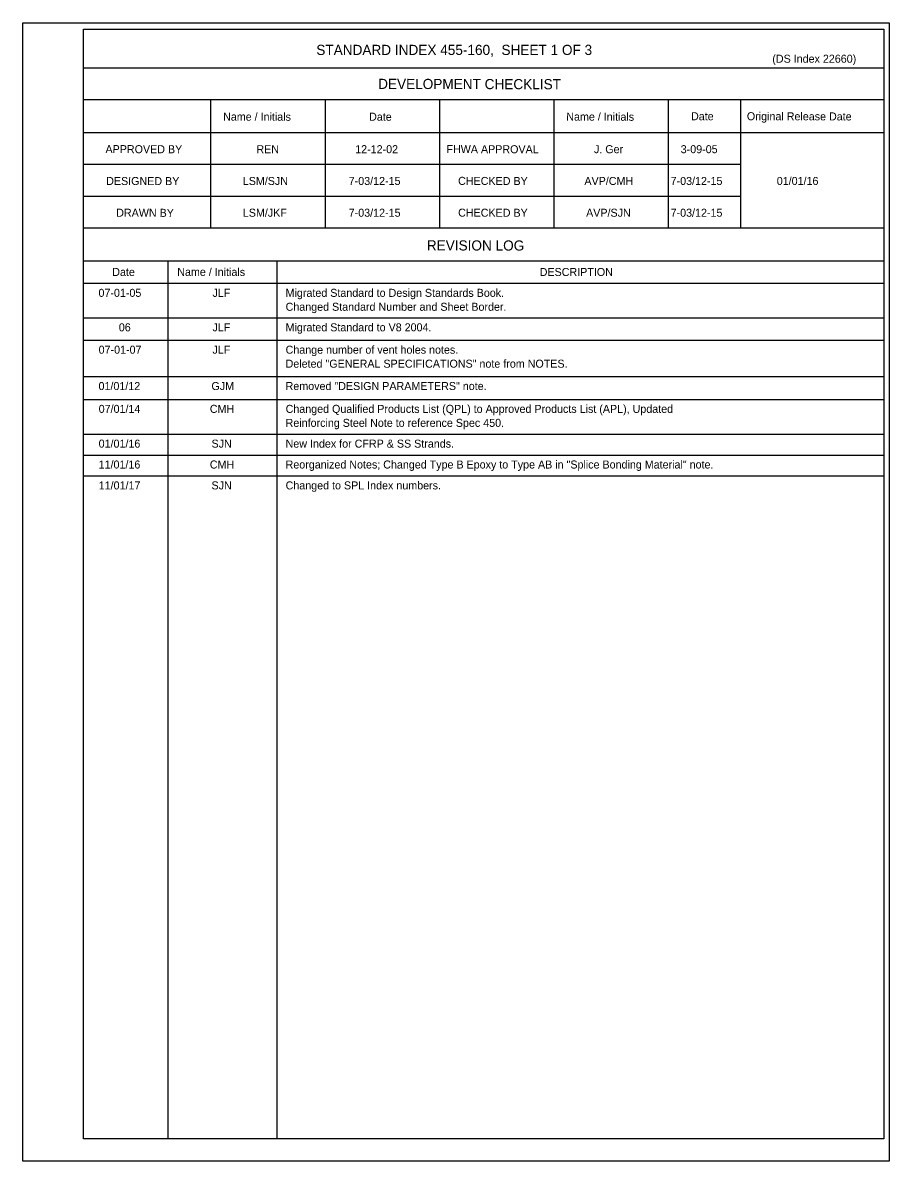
# Model space of a CAD drawing. Extents: x 120462 to 120592, y 120515 to 120635.
# Drawn here: x 120570.2 to 120592.01, y 120600.69 to 120629.36 of the extents above; entities that cross this region are included whole.
import ezdxf

# ---------------------------------------------------------------- set-up
doc = ezdxf.new("R2010")
doc.units = 0
for name, color, linetype in [('AdhocPoint_dp', 7, 'Continuous'), ('Border', 7, 'Continuous'), ('SheetBorder_dp', 7, 'Continuous')]:
    doc.layers.add(name, color=color, linetype=linetype)

msp = doc.modelspace()

# ---------------------------------------------------------------- linework, layer by layer
at = {"layer": 'AdhocPoint_dp'}
for p, q in [((120571.728, 120621.929), (120591.874, 120621.929)), ((120571.728, 120621.365), (120591.874, 120621.365)), ((120571.728, 120620.45), (120591.874, 120620.45)), ((120571.728, 120619.875), (120591.874, 120619.875)), ((120571.728, 120619), (120591.874, 120619)), ((120571.728, 120618.474), (120591.874, 120618.474)), ((120571.728, 120617.948), (120591.874, 120617.948))]:
    msp.add_line(p, q, dxfattribs=at)
at = {"layer": 'Border'}
for p, q in [((120591.874, 120628.217), (120571.727, 120628.217)), ((120591.874, 120627.417), (120571.727, 120627.417)), ((120574.927, 120627.417), (120574.927, 120624.189)), ((120577.807, 120627.417), (120577.807, 120624.189)), ((120580.687, 120627.417), (120580.687, 120624.189)), ((120583.567, 120627.417), (120583.567, 120624.189)), ((120586.447, 120627.417), (120586.447, 120624.189)), ((120588.262, 120627.417), (120588.262, 120624.189)), ((120591.874, 120626.589), (120571.727, 120626.589)), ((120588.262, 120625.789), (120571.727, 120625.789)), ((120588.262, 120624.989), (120571.727, 120624.989)), ((120591.874, 120624.189), (120571.727, 120624.189)), ((120591.874, 120623.361), (120571.727, 120623.361)), ((120573.848, 120623.361), (120573.848, 120601.255)), ((120576.59, 120623.361), (120576.59, 120601.255)), ((120591.874, 120622.797), (120571.727, 120622.797))]:
    msp.add_line(p, q, dxfattribs=at)
msp.add_lwpolyline([(120571.728, 120629.197), (120591.874, 120629.197), (120591.874, 120601.255), (120571.728, 120601.255)], close=True, dxfattribs=at)
at = {"layer": 'SheetBorder_dp'}
msp.add_line((120570.197, 120600.693), (120570.197, 120600.693), dxfattribs=at)
msp.add_lwpolyline([(120570.197, 120629.36), (120592.01, 120629.36), (120592.01, 120600.693), (120570.197, 120600.693)], close=True, dxfattribs=at)

# ---------------------------------------------------------------- texts
at = {"layer": 'Border'}
for s, height, p in [('STANDARD INDEX 455-160,  SHEET 1 OF 3', 0.256, (120577.587, 120628.549)), ('(DS Index 22660)', 0.2016, (120589.067, 120628.354)), ('REN', 0.2016, (120576.079, 120626.076)), ('12-12-02', 0.2016, (120578.566, 120626.076)), ('J. Ger', 0.2016, (120584.577, 120626.076)), ('3-09-05', 0.2016, (120586.761, 120626.076)), ('LSM/SJN', 0.2016, (120575.736, 120625.276)), ('7-03/12-15', 0.2016, (120578.403, 120625.276)), ('AVP/CMH', 0.2016, (120584.336, 120625.276)), ('7-03/12-15', 0.2016, (120586.507, 120625.276)), ('01/01/16', 0.2016, (120589.179, 120625.276)), ('LSM/JKF', 0.2016, (120575.738, 120624.476)), ('7-03/12-15', 0.2016, (120578.403, 120624.476)), ('AVP/SJN', 0.2016, (120584.379, 120624.476)), ('7-03/12-15', 0.2016, (120586.507, 120624.476)), ('DESCRIPTION', 0.2016, (120583.211, 120622.984)), ('07-01-05', 0.2016, (120572.103, 120622.459)), ('JLF', 0.2016, (120574.974, 120622.459)), ('Migrated Standard to Design Standards Book.', 0.2016, (120576.814, 120622.459)), ('Changed Standard Number and Sheet Border.', 0.2016, (120576.814, 120622.108)), ('06', 0.2016, (120572.615, 120621.591)), ('JLF', 0.2016, (120574.974, 120621.591)), ('Migrated Standard to V8 2004.', 0.2016, (120576.814, 120621.591)), ('07-01-07', 0.2016, (120572.107, 120621.027)), ('JLF', 0.2016, (120574.974, 120621.027)), ('Change number of vent holes notes.', 0.2016, (120576.814, 120621.027)), ('Deleted "GENERAL SPECIFICATIONS" note from NOTES.', 0.2016, (120576.814, 120620.675)), ('01/01/12', 0.2016, (120572.104, 120620.112)), ('GJM', 0.2016, (120574.947, 120620.112)), ('Removed "DESIGN PARAMETERS" note.', 0.2016, (120576.814, 120620.112)), ('07/01/14', 0.2016, (120572.108, 120619.537)), ('CMH', 0.2016, (120574.906, 120619.537)), ('Changed Qualified Products List (QPL) to Approved Products List (APL), Updated', 0.2016, (120576.814, 120619.537)), ('Reinforcing Steel Note to reference Spec 450.', 0.2016, (120576.814, 120619.185)), ('01/01/16', 0.2016, (120572.107, 120618.662)), ('SJN', 0.2016, (120574.949, 120618.662)), ('New Index for CFRP & SS Strands.', 0.2016, (120576.814, 120618.662)), ('11/01/16', 0.2016, (120572.107, 120618.136)), ('CMH', 0.2016, (120574.906, 120618.136)), ('Reorganized Notes; Changed Type B Epoxy to Type AB in "Splice Bonding Material" note.', 0.2016, (120576.814, 120618.136)), ('11/01/17', 0.2016, (120572.109, 120617.61)), ('SJN', 0.2016, (120574.949, 120617.61)), ('Changed to SPL Index numbers.', 0.2016, (120576.814, 120617.61))]:
    msp.add_text(s, height=height, dxfattribs=at).set_placement(p)
for s, height, p in [('DEVELOPMENT CHECKLIST', 0.256, (120579.143, 120627.694)), ('Name / Initials', 0.2016, (120575.24, 120626.896)), ('Date', 0.2016, (120578.915, 120626.894)), ('Name / Initials', 0.2016, (120583.88, 120626.896)), ('Date', 0.2016, (120587.02, 120626.906)), ('Original Release Date', 0.2016, (120588.426, 120626.906)), ('APPROVED BY', 0.2016, (120572.279, 120626.078)), ('FHWA APPROVAL', 0.2016, (120580.863, 120626.078)), ('DESIGNED BY', 0.2016, (120572.296, 120625.276)), ('CHECKED BY', 0.2016, (120581.157, 120625.278)), ('DRAWN BY', 0.2016, (120572.549, 120624.476)), ('CHECKED BY', 0.2016, (120581.157, 120624.478)), ('REVISION LOG', 0.256, (120580.369, 120623.628)), ('Date', 0.2016, (120572.45, 120622.985)), ('Name / Initials', 0.2016, (120574.086, 120622.987))]:
    msp.add_text(s, height=height, rotation=359.8756, dxfattribs=at).set_placement(p)

doc.saveas('drawing.dxf')
